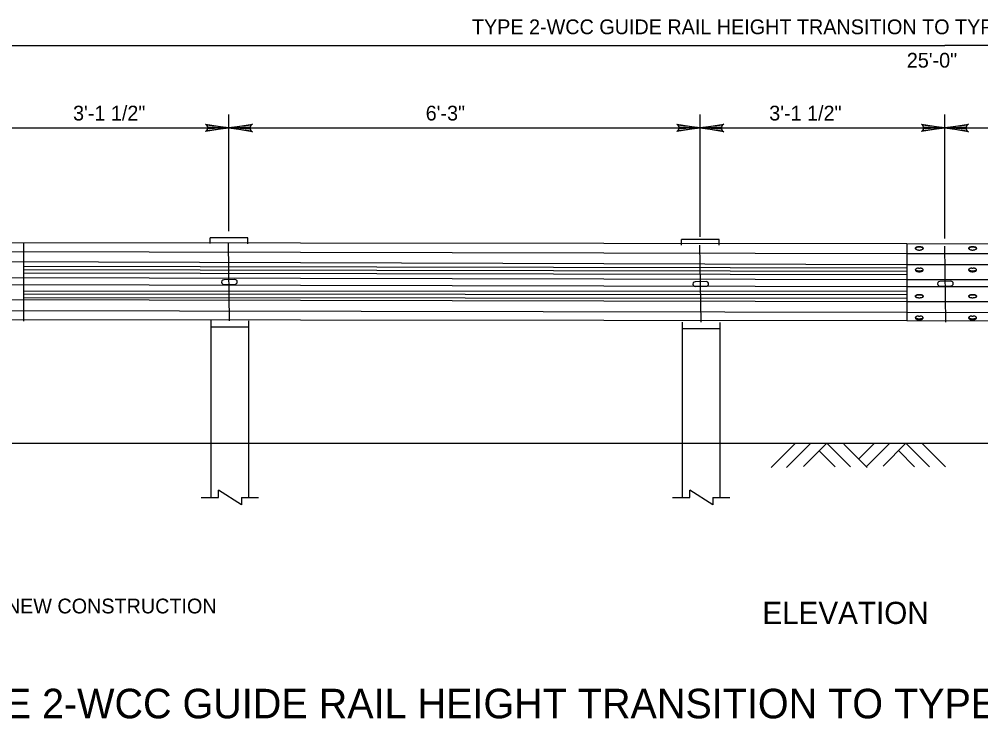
# Model space of a CAD drawing. Extents: x 637628 to 640188, y 298266 to 300751.
# Drawn here: x 639374.9 to 639570.1, y 300419.5 to 300561.4 of the extents above; entities that cross this region are included whole.
import ezdxf

# ---------------------------------------------------------------- set-up
doc = ezdxf.new("R2010")
doc.units = 0
for name, color, linetype in [('2', 7, 'Continuous'), ('S-ABUT-CONC', 7, 'Continuous'), ('S-ANNO-CELL', 7, 'Continuous'), ('S-ANNO-T120-01', 7, 'Continuous')]:
    doc.layers.add(name, color=color, linetype=linetype)

msp = doc.modelspace()

# ---------------------------------------------------------------- linework, layer by layer
at = {"layer": '2'}
for p, q in [((639538.91, 300475.36), (639534.18, 300470.63)), ((639543.68, 300470.59), (639538.91, 300475.36)), ((639548.51, 300475.33), (639545.37, 300472.18)), ((639551.62, 300475.33), (639546.85, 300470.56)), ((639554.93, 300475.36), (639550.3, 300470.73)), ((639559.71, 300470.59), (639554.93, 300475.36)), ((639562.95, 300470.56), (639558.15, 300475.36)), ((639532.39, 300475.23), (639527.62, 300470.46)), ((639535.5, 300475.23), (639530.72, 300470.46)), ((639540.57, 300470.59), (639537.35, 300473.81)), ((639547.09, 300470.46), (639542.36, 300475.19)), ((639556.7, 300470.6), (639553.48, 300473.82))]:
    msp.add_line(p, q, dxfattribs=at)
for points in [[(639412.98, 300539.94), (639413.15, 300539.61), (639417.52, 300539.37), (639412.98, 300539.94), (639412.75, 300540.14), (639417.52, 300539.37), (639413.15, 300539.16), (639412.99, 300538.83), (639417.52, 300539.37), (639412.75, 300538.61), (639412.99, 300538.83)], [(639422.06, 300538.8), (639421.89, 300539.13), (639417.52, 300539.37), (639422.06, 300538.8), (639422.29, 300538.6), (639417.52, 300539.37), (639421.89, 300539.59), (639422.05, 300539.91), (639417.52, 300539.37), (639422.29, 300540.13), (639422.05, 300539.91)], [(639508.65, 300539.94), (639508.82, 300539.61), (639513.19, 300539.37), (639508.65, 300539.94), (639508.42, 300540.14), (639513.19, 300539.37), (639508.83, 300539.16), (639508.66, 300538.83), (639513.19, 300539.37), (639508.42, 300538.61), (639508.66, 300538.83)], [(639517.73, 300538.8), (639517.56, 300539.13), (639513.19, 300539.37), (639517.73, 300538.8), (639517.96, 300538.6), (639513.19, 300539.37), (639517.56, 300539.59), (639517.72, 300539.91), (639513.19, 300539.37), (639517.96, 300540.13), (639517.72, 300539.91)], [(639558.31, 300539.94), (639558.48, 300539.61), (639562.85, 300539.37), (639558.31, 300539.94), (639558.08, 300540.14), (639562.85, 300539.37), (639558.49, 300539.16), (639558.32, 300538.83), (639562.85, 300539.37), (639558.08, 300538.61), (639558.32, 300538.83)], [(639567.39, 300538.8), (639567.22, 300539.13), (639562.85, 300539.37), (639567.39, 300538.8), (639567.62, 300538.6), (639562.85, 300539.37), (639567.22, 300539.59), (639567.38, 300539.91), (639562.85, 300539.37), (639567.62, 300540.13), (639567.38, 300539.91)]]:
    msp.add_lwpolyline(points, dxfattribs=at)
at = {"layer": 'S-ABUT-CONC'}
for p, q in [((639367.86, 300556.1), (639562.85, 300556.1)), ((639807.71, 300556.1), (639562.85, 300556.1)), ((639417.52, 300518.38), (639417.52, 300542.08)), ((639513.19, 300517.88), (639513.19, 300542.08)), ((639513.19, 300517.25), (639513.19, 300542.08)), ((639562.85, 300516.92), (639562.85, 300542.08)), ((639367.86, 300539.37), (639465.36, 300539.37)), ((639465.36, 300539.37), (639513.19, 300539.37)), ((639513.19, 300539.37), (639562.85, 300539.37)), ((639562.85, 300539.37), (639660.56, 300539.37))]:
    msp.add_line(p, q, dxfattribs=at)
at = {"layer": 'S-ANNO-CELL'}
for p, q in [((639413.7, 300515.89), (639413.7, 300517.07)), ((639421.34, 300517.07), (639413.7, 300517.07)), ((639421.34, 300515.86), (639421.34, 300517.07)), ((639509.37, 300515.57), (639509.37, 300516.75)), ((639517.01, 300516.75), (639509.37, 300516.75)), ((639517.01, 300515.55), (639517.01, 300516.75)), ((639555.11, 300515.82), (639359.91, 300516.06)), ((639375.82, 300516.01), (639375.82, 300500.12)), ((639417.66, 300500.24), (639417.45, 300515.88)), ((639513.35, 300499.92), (639513.14, 300515.56)), ((639555.11, 300515.82), (639555.11, 300500.19)), ((639750.31, 300515.42), (639555.11, 300515.82)), ((639557.49, 300515.29), (639557.81, 300515.29)), ((639557.49, 300515.17), (639557.49, 300515.29)), ((639557.81, 300515.17), (639557.49, 300515.17)), ((639557.49, 300514.57), (639557.81, 300514.57)), ((639557.81, 300515.17), (639557.81, 300515.29)), ((639563.06, 300499.93), (639562.85, 300515.4)), ((639568.31, 300515.29), (639568.63, 300515.29)), ((639568.31, 300515.17), (639568.31, 300515.29)), ((639568.63, 300515.17), (639568.31, 300515.17)), ((639568.31, 300514.57), (639568.63, 300514.57)), ((639568.63, 300515.17), (639568.63, 300515.29)), ((639555.11, 300513.81), (639359.91, 300514.22)), ((639750.31, 300513.57), (639555.11, 300513.81)), ((639555.11, 300511.6), (639359.91, 300512.24)), ((639555.11, 300510.92), (639375.82, 300511.26)), ((639555.11, 300510.23), (639375.82, 300510.58)), ((639750.31, 300511.36), (639555.11, 300511.6)), ((639557.49, 300510.91), (639557.81, 300510.91)), ((639568.31, 300510.91), (639568.63, 300510.91)), ((639555.11, 300508.55), (639359.91, 300508.95)), ((639555.11, 300509.54), (639375.82, 300509.89)), ((639418.73, 300508.59), (639416.5, 300508.56)), ((639750.31, 300508.31), (639555.11, 300508.55)), ((639557.49, 300510.31), (639557.49, 300510.19)), ((639557.81, 300510.31), (639557.49, 300510.31)), ((639557.49, 300510.19), (639557.81, 300510.19)), ((639557.81, 300510.31), (639557.81, 300510.19)), ((639568.31, 300510.31), (639568.31, 300510.19)), ((639568.63, 300510.31), (639568.31, 300510.31)), ((639568.31, 300510.19), (639568.63, 300510.19)), ((639568.63, 300510.31), (639568.63, 300510.19)), ((639555.11, 300507.14), (639359.91, 300507.54)), ((639416.52, 300507.6), (639418.75, 300507.63)), ((639514.4, 300508.18), (639512.18, 300508.15)), ((639512.19, 300507.2), (639514.42, 300507.23)), ((639750.31, 300506.9), (639555.11, 300507.14)), ((639564.06, 300508.26), (639561.84, 300508.23)), ((639561.85, 300507.28), (639564.08, 300507.31)), ((639555.11, 300506.16), (639375.82, 300506.24)), ((639555.11, 300505.47), (639375.82, 300505.61)), ((639555.11, 300504.78), (639375.82, 300504.85)), ((639557.49, 300505.56), (639557.81, 300505.56)), ((639557.49, 300505.45), (639557.49, 300505.56)), ((639557.81, 300505.45), (639557.49, 300505.45)), ((639557.49, 300504.85), (639557.81, 300504.85)), ((639557.81, 300505.45), (639557.81, 300505.56)), ((639568.31, 300505.56), (639568.63, 300505.56)), ((639568.31, 300505.45), (639568.31, 300505.56)), ((639568.63, 300505.45), (639568.31, 300505.45)), ((639568.31, 300504.85), (639568.63, 300504.85)), ((639568.63, 300505.45), (639568.63, 300505.56)), ((639555.11, 300504.09), (639359.91, 300504.49)), ((639750.31, 300503.85), (639555.11, 300504.09)), ((639555.11, 300501.88), (639359.91, 300502.28)), ((639750.31, 300501.64), (639555.11, 300501.88)), ((639557.49, 300501.18), (639557.81, 300501.18)), ((639568.31, 300501.18), (639568.63, 300501.18)), ((639555.11, 300500.19), (639359.91, 300500.43)), ((639413.91, 300493.59), (639413.91, 300500.25)), ((639421.55, 300498.9), (639413.91, 300498.9)), ((639421.55, 300493.59), (639421.55, 300500.22)), ((639509.58, 300494.89), (639509.58, 300499.94)), ((639517.22, 300494.89), (639517.22, 300499.91)), ((639750.31, 300499.79), (639555.11, 300500.19)), ((639557.49, 300500.58), (639557.49, 300500.47)), ((639557.81, 300500.58), (639557.49, 300500.58)), ((639557.49, 300500.47), (639557.81, 300500.47)), ((639557.81, 300500.58), (639557.81, 300500.47)), ((639568.31, 300500.58), (639568.31, 300500.47)), ((639568.63, 300500.58), (639568.31, 300500.58)), ((639568.31, 300500.47), (639568.63, 300500.47)), ((639568.63, 300500.58), (639568.63, 300500.47)), ((639517.22, 300498.59), (639509.58, 300498.59)), ((639509.58, 300475.37), (639509.58, 300494.89)), ((639517.22, 300475.37), (639517.22, 300494.89)), ((639413.91, 300475.37), (639413.91, 300493.59)), ((639421.55, 300475.37), (639421.55, 300493.59)), ((639291.81, 300475.37), (639555.11, 300475.37)), ((639413.91, 300464.35), (639413.91, 300475.37)), ((639421.55, 300464.35), (639421.55, 300475.37)), ((639509.58, 300464.35), (639509.58, 300475.37)), ((639517.22, 300464.35), (639517.22, 300475.37)), ((639555.11, 300475.37), (639877.39, 300475.37)), ((639415.41, 300464.35), (639415.41, 300465.85)), ((639420.05, 300462.85), (639415.41, 300465.85)), ((639511.08, 300464.35), (639511.08, 300465.85)), ((639515.72, 300462.85), (639511.08, 300465.85)), ((639411.91, 300464.35), (639415.41, 300464.35)), ((639420.05, 300464.35), (639420.05, 300462.85)), ((639420.05, 300464.35), (639423.55, 300464.35)), ((639507.58, 300464.35), (639511.08, 300464.35)), ((639515.72, 300464.35), (639515.72, 300462.85)), ((639515.72, 300464.35), (639519.22, 300464.35))]:
    msp.add_line(p, q, dxfattribs=at)
for points in [[(639557.49, 300514.57), (639557.38, 300514.58), (639557.27, 300514.59), (639557.17, 300514.62), (639557.08, 300514.66), (639557, 300514.7), (639556.94, 300514.75), (639556.89, 300514.81), (639556.87, 300514.87), (639556.86, 300514.93), (639556.87, 300514.99), (639556.89, 300515.05), (639556.94, 300515.11), (639557, 300515.16), (639557.08, 300515.2), (639557.17, 300515.24), (639557.27, 300515.26), (639557.38, 300515.28), (639557.49, 300515.29)], [(639557.49, 300515.17), (639557.38, 300515.17), (639557.27, 300515.15), (639557.17, 300515.13), (639557.08, 300515.09), (639557, 300515.05), (639556.94, 300515), (639556.89, 300514.94), (639556.87, 300514.88), (639556.86, 300514.87)], [(639557.81, 300515.29), (639557.92, 300515.28), (639558.03, 300515.26), (639558.13, 300515.24), (639558.22, 300515.2), (639558.3, 300515.16), (639558.36, 300515.11), (639558.41, 300515.05), (639558.44, 300514.99), (639558.45, 300514.93), (639558.44, 300514.87), (639558.41, 300514.81), (639558.36, 300514.75), (639558.3, 300514.7), (639558.22, 300514.66), (639558.13, 300514.62), (639558.03, 300514.59), (639557.92, 300514.58), (639557.81, 300514.57)], [(639558.44, 300514.87), (639558.44, 300514.88), (639558.41, 300514.94), (639558.36, 300515), (639558.3, 300515.05), (639558.22, 300515.09), (639558.13, 300515.13), (639558.03, 300515.15), (639557.92, 300515.17), (639557.81, 300515.17)], [(639568.31, 300514.57), (639568.2, 300514.58), (639568.1, 300514.59), (639567.99, 300514.62), (639567.9, 300514.66), (639567.83, 300514.7), (639567.76, 300514.75), (639567.71, 300514.81), (639567.69, 300514.87), (639567.68, 300514.93), (639567.69, 300514.99), (639567.71, 300515.05), (639567.76, 300515.11), (639567.83, 300515.16), (639567.9, 300515.2), (639567.99, 300515.24), (639568.1, 300515.26), (639568.2, 300515.28), (639568.31, 300515.29)], [(639568.31, 300515.17), (639568.2, 300515.17), (639568.1, 300515.15), (639567.99, 300515.13), (639567.9, 300515.09), (639567.83, 300515.05), (639567.76, 300515), (639567.71, 300514.94), (639567.69, 300514.88), (639567.68, 300514.87)], [(639568.63, 300515.29), (639568.74, 300515.28), (639568.85, 300515.26), (639568.95, 300515.24), (639569.04, 300515.2), (639569.12, 300515.16), (639569.18, 300515.11), (639569.23, 300515.05), (639569.26, 300514.99), (639569.27, 300514.93), (639569.26, 300514.87), (639569.23, 300514.81), (639569.18, 300514.75), (639569.12, 300514.7), (639569.04, 300514.66), (639568.95, 300514.62), (639568.85, 300514.59), (639568.74, 300514.58), (639568.63, 300514.57)], [(639569.26, 300514.87), (639569.26, 300514.88), (639569.23, 300514.94), (639569.18, 300515), (639569.12, 300515.05), (639569.04, 300515.09), (639568.95, 300515.13), (639568.85, 300515.15), (639568.74, 300515.17), (639568.63, 300515.17)], [(639557.49, 300510.91), (639557.38, 300510.9), (639557.27, 300510.89), (639557.17, 300510.86), (639557.08, 300510.82), (639557, 300510.78), (639556.94, 300510.73), (639556.89, 300510.67), (639556.87, 300510.61), (639556.86, 300510.55), (639556.87, 300510.49), (639556.89, 300510.43), (639556.94, 300510.37), (639557, 300510.32), (639557.08, 300510.28), (639557.17, 300510.24), (639557.27, 300510.22), (639557.38, 300510.2), (639557.49, 300510.19)], [(639557.49, 300510.31), (639557.38, 300510.31), (639557.27, 300510.33), (639557.17, 300510.35), (639557.08, 300510.39), (639557, 300510.43), (639556.94, 300510.48), (639556.89, 300510.54), (639556.87, 300510.6), (639556.86, 300510.61)], [(639557.81, 300510.19), (639557.92, 300510.2), (639558.03, 300510.22), (639558.13, 300510.24), (639558.22, 300510.28), (639558.3, 300510.32), (639558.36, 300510.37), (639558.41, 300510.43), (639558.44, 300510.49), (639558.45, 300510.55), (639558.44, 300510.61), (639558.41, 300510.67), (639558.36, 300510.73), (639558.3, 300510.78), (639558.22, 300510.82), (639558.13, 300510.86), (639558.03, 300510.89), (639557.92, 300510.9), (639557.81, 300510.91)], [(639558.44, 300510.61), (639558.44, 300510.6), (639558.41, 300510.54), (639558.36, 300510.48), (639558.3, 300510.43), (639558.22, 300510.39), (639558.13, 300510.35), (639558.03, 300510.33), (639557.92, 300510.31), (639557.81, 300510.31)], [(639568.31, 300510.91), (639568.2, 300510.9), (639568.1, 300510.89), (639567.99, 300510.86), (639567.9, 300510.82), (639567.83, 300510.78), (639567.76, 300510.73), (639567.71, 300510.67), (639567.69, 300510.61), (639567.68, 300510.55), (639567.69, 300510.49), (639567.71, 300510.43), (639567.76, 300510.37), (639567.83, 300510.32), (639567.9, 300510.28), (639567.99, 300510.24), (639568.1, 300510.22), (639568.2, 300510.2), (639568.31, 300510.19)], [(639568.31, 300510.31), (639568.2, 300510.31), (639568.1, 300510.33), (639567.99, 300510.35), (639567.9, 300510.39), (639567.83, 300510.43), (639567.76, 300510.48), (639567.71, 300510.54), (639567.69, 300510.6), (639567.68, 300510.61)], [(639568.63, 300510.19), (639568.74, 300510.2), (639568.85, 300510.22), (639568.95, 300510.24), (639569.04, 300510.28), (639569.12, 300510.32), (639569.18, 300510.37), (639569.23, 300510.43), (639569.26, 300510.49), (639569.27, 300510.55), (639569.26, 300510.61), (639569.23, 300510.67), (639569.18, 300510.73), (639569.12, 300510.78), (639569.04, 300510.82), (639568.95, 300510.86), (639568.85, 300510.89), (639568.74, 300510.9), (639568.63, 300510.91)], [(639569.26, 300510.61), (639569.26, 300510.6), (639569.23, 300510.54), (639569.18, 300510.48), (639569.12, 300510.43), (639569.04, 300510.39), (639568.95, 300510.35), (639568.85, 300510.33), (639568.74, 300510.31), (639568.63, 300510.31)], [(639557.49, 300504.85), (639557.38, 300504.85), (639557.27, 300504.87), (639557.17, 300504.9), (639557.08, 300504.93), (639557, 300504.98), (639556.94, 300505.03), (639556.89, 300505.08), (639556.87, 300505.14), (639556.86, 300505.21), (639556.87, 300505.27), (639556.89, 300505.33), (639556.94, 300505.38), (639557, 300505.43), (639557.08, 300505.48), (639557.17, 300505.51), (639557.27, 300505.54), (639557.38, 300505.56), (639557.49, 300505.56)], [(639557.49, 300505.45), (639557.38, 300505.45), (639557.27, 300505.43), (639557.17, 300505.4), (639557.08, 300505.37), (639557, 300505.32), (639556.94, 300505.27), (639556.89, 300505.22), (639556.87, 300505.16), (639556.86, 300505.15)], [(639557.81, 300505.56), (639557.92, 300505.56), (639558.03, 300505.54), (639558.13, 300505.51), (639558.22, 300505.48), (639558.3, 300505.43), (639558.36, 300505.38), (639558.41, 300505.33), (639558.44, 300505.27), (639558.45, 300505.21), (639558.44, 300505.14), (639558.41, 300505.08), (639558.36, 300505.03), (639558.3, 300504.98), (639558.22, 300504.93), (639558.13, 300504.9), (639558.03, 300504.87), (639557.92, 300504.85), (639557.81, 300504.85)], [(639558.44, 300505.15), (639558.44, 300505.16), (639558.41, 300505.22), (639558.36, 300505.27), (639558.3, 300505.32), (639558.22, 300505.37), (639558.13, 300505.4), (639558.03, 300505.43), (639557.92, 300505.45), (639557.81, 300505.45)], [(639568.31, 300504.85), (639568.2, 300504.85), (639568.1, 300504.87), (639567.99, 300504.9), (639567.9, 300504.93), (639567.83, 300504.98), (639567.76, 300505.03), (639567.71, 300505.08), (639567.69, 300505.14), (639567.68, 300505.21), (639567.69, 300505.27), (639567.71, 300505.33), (639567.76, 300505.38), (639567.83, 300505.43), (639567.9, 300505.48), (639567.99, 300505.51), (639568.1, 300505.54), (639568.2, 300505.56), (639568.31, 300505.56)], [(639568.31, 300505.45), (639568.2, 300505.45), (639568.1, 300505.43), (639567.99, 300505.4), (639567.9, 300505.37), (639567.83, 300505.32), (639567.76, 300505.27), (639567.71, 300505.22), (639567.69, 300505.16), (639567.68, 300505.15)], [(639568.63, 300505.56), (639568.74, 300505.56), (639568.85, 300505.54), (639568.95, 300505.51), (639569.04, 300505.48), (639569.12, 300505.43), (639569.18, 300505.38), (639569.23, 300505.33), (639569.26, 300505.27), (639569.27, 300505.21), (639569.26, 300505.14), (639569.23, 300505.08), (639569.18, 300505.03), (639569.12, 300504.98), (639569.04, 300504.93), (639568.95, 300504.9), (639568.85, 300504.87), (639568.74, 300504.85), (639568.63, 300504.85)], [(639569.26, 300505.15), (639569.26, 300505.16), (639569.23, 300505.22), (639569.18, 300505.27), (639569.12, 300505.32), (639569.04, 300505.37), (639568.95, 300505.4), (639568.85, 300505.43), (639568.74, 300505.45), (639568.63, 300505.45)], [(639557.49, 300501.18), (639557.38, 300501.18), (639557.27, 300501.16), (639557.17, 300501.14), (639557.08, 300501.1), (639557, 300501.06), (639556.94, 300501.01), (639556.89, 300500.95), (639556.87, 300500.89), (639556.86, 300500.83), (639556.87, 300500.77), (639556.89, 300500.71), (639556.94, 300500.65), (639557, 300500.6), (639557.08, 300500.55), (639557.17, 300500.52), (639557.27, 300500.49), (639557.38, 300500.48), (639557.49, 300500.47)], [(639557.49, 300500.58), (639557.38, 300500.59), (639557.27, 300500.6), (639557.17, 300500.63), (639557.08, 300500.67), (639557, 300500.71), (639556.94, 300500.76), (639556.89, 300500.82), (639556.87, 300500.88), (639556.86, 300500.88)], [(639557.81, 300500.47), (639557.92, 300500.48), (639558.03, 300500.49), (639558.13, 300500.52), (639558.22, 300500.55), (639558.3, 300500.6), (639558.36, 300500.65), (639558.41, 300500.71), (639558.44, 300500.77), (639558.45, 300500.83), (639558.44, 300500.89), (639558.41, 300500.95), (639558.36, 300501.01), (639558.3, 300501.06), (639558.22, 300501.1), (639558.13, 300501.14), (639558.03, 300501.16), (639557.92, 300501.18), (639557.81, 300501.18)], [(639558.44, 300500.88), (639558.44, 300500.88), (639558.41, 300500.82), (639558.36, 300500.76), (639558.3, 300500.71), (639558.22, 300500.67), (639558.13, 300500.63), (639558.03, 300500.6), (639557.92, 300500.59), (639557.81, 300500.58)], [(639568.31, 300501.18), (639568.2, 300501.18), (639568.1, 300501.16), (639567.99, 300501.14), (639567.9, 300501.1), (639567.83, 300501.06), (639567.76, 300501.01), (639567.71, 300500.95), (639567.69, 300500.89), (639567.68, 300500.83), (639567.69, 300500.77), (639567.71, 300500.71), (639567.76, 300500.65), (639567.83, 300500.6), (639567.9, 300500.55), (639567.99, 300500.52), (639568.1, 300500.49), (639568.2, 300500.48), (639568.31, 300500.47)], [(639568.31, 300500.58), (639568.2, 300500.59), (639568.1, 300500.6), (639567.99, 300500.63), (639567.9, 300500.67), (639567.83, 300500.71), (639567.76, 300500.76), (639567.71, 300500.82), (639567.69, 300500.88), (639567.68, 300500.88)], [(639568.63, 300500.47), (639568.74, 300500.48), (639568.85, 300500.49), (639568.95, 300500.52), (639569.04, 300500.55), (639569.12, 300500.6), (639569.18, 300500.65), (639569.23, 300500.71), (639569.26, 300500.77), (639569.27, 300500.83), (639569.26, 300500.89), (639569.23, 300500.95), (639569.18, 300501.01), (639569.12, 300501.06), (639569.04, 300501.1), (639568.95, 300501.14), (639568.85, 300501.16), (639568.74, 300501.18), (639568.63, 300501.18)], [(639569.26, 300500.88), (639569.26, 300500.88), (639569.23, 300500.82), (639569.18, 300500.76), (639569.12, 300500.71), (639569.04, 300500.67), (639568.95, 300500.63), (639568.85, 300500.6), (639568.74, 300500.59), (639568.63, 300500.58)]]:
    msp.add_lwpolyline(points, dxfattribs=at)
for centre, start, end in [((639416.51, 300508.08), 90.7767, 270.7767), ((639418.74, 300508.11), 270.7767, 90.7767), ((639512.18, 300507.67), 90.7767, 270.7767), ((639514.41, 300507.7), 270.7767, 90.7767), ((639561.84, 300507.75), 90.7767, 270.7767), ((639564.07, 300507.78), 270.7767, 90.7767)]:
    msp.add_arc(centre, 0.477, start, end, dxfattribs=at)

# ---------------------------------------------------------------- texts
at = {"layer": 'S-ABUT-CONC'}
for s, p in [('TYPE 2-WCC GUIDE RAIL HEIGHT TRANSITION TO TYPE 31-S GUIDE RAIL', (639466.85, 300558.38)), ('25\'-0"', (639555.13, 300551.6)), ('3\'-1 1/2"', (639385.87, 300540.87)), ('6\'-3"', (639457.46, 300540.87)), ('3\'-1 1/2"', (639527.2, 300540.87)), ('OR 32" HEIGHT FOR NEW CONSTRUCTION', (639332.24, 300440.84))]:
    msp.add_text(s, height=3, dxfattribs=at).set_placement(p)
at = {"layer": 'S-ANNO-T120-01'}
for s, height, p in [('ELEVATION', 4.5, (639525.8, 300438.7)), ('TYPE 2-WCC GUIDE RAIL HEIGHT TRANSITION TO TYPE 31-S GUIDE RAIL', 6, (639356.39, 300419.55))]:
    msp.add_text(s, height=height, dxfattribs=at).set_placement(p)

doc.saveas('drawing.dxf')
